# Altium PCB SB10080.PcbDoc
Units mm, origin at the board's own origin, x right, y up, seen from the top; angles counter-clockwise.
Board outline 100 x 80 mm, 2 copper layers (Top Layer, Bottom Layer); 0 components, 0 nets, 4 pads, 0 vias.
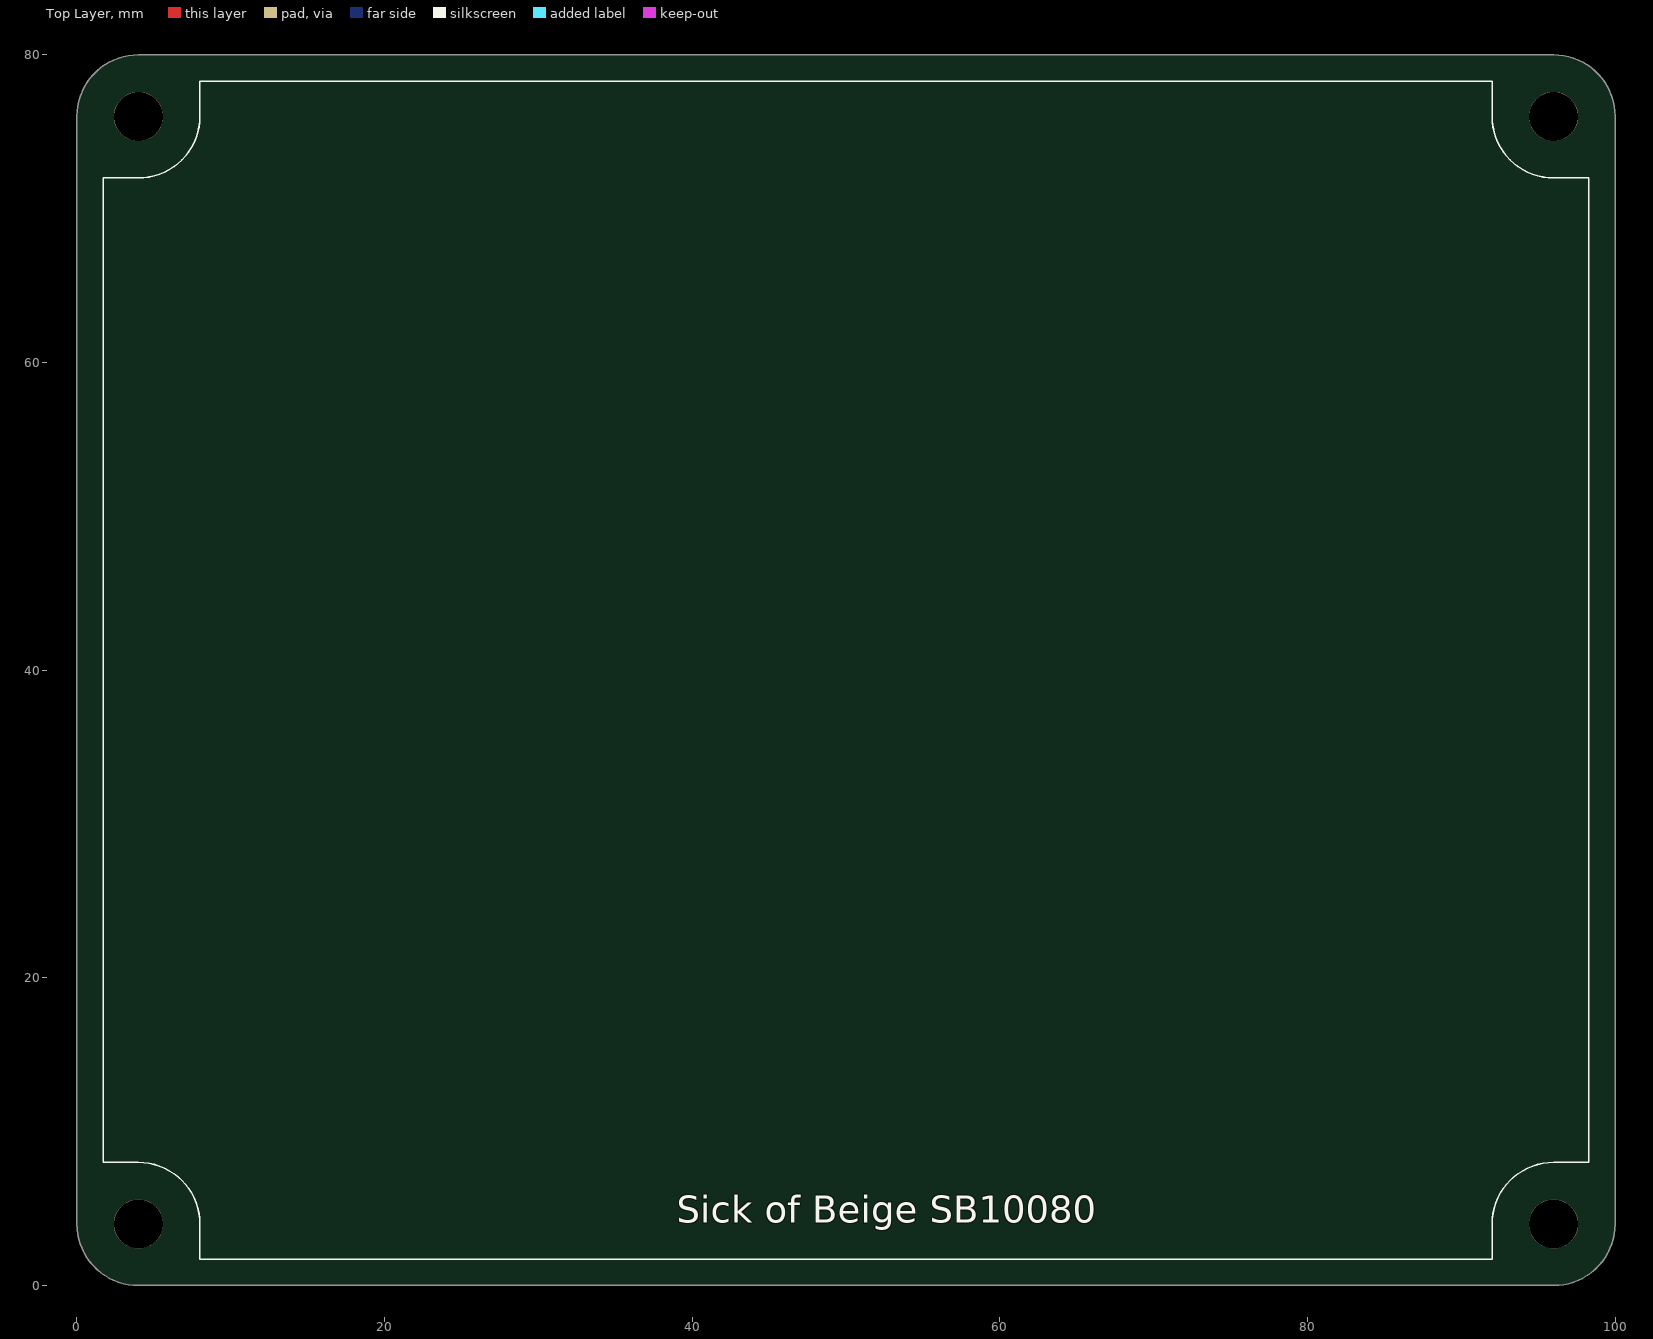
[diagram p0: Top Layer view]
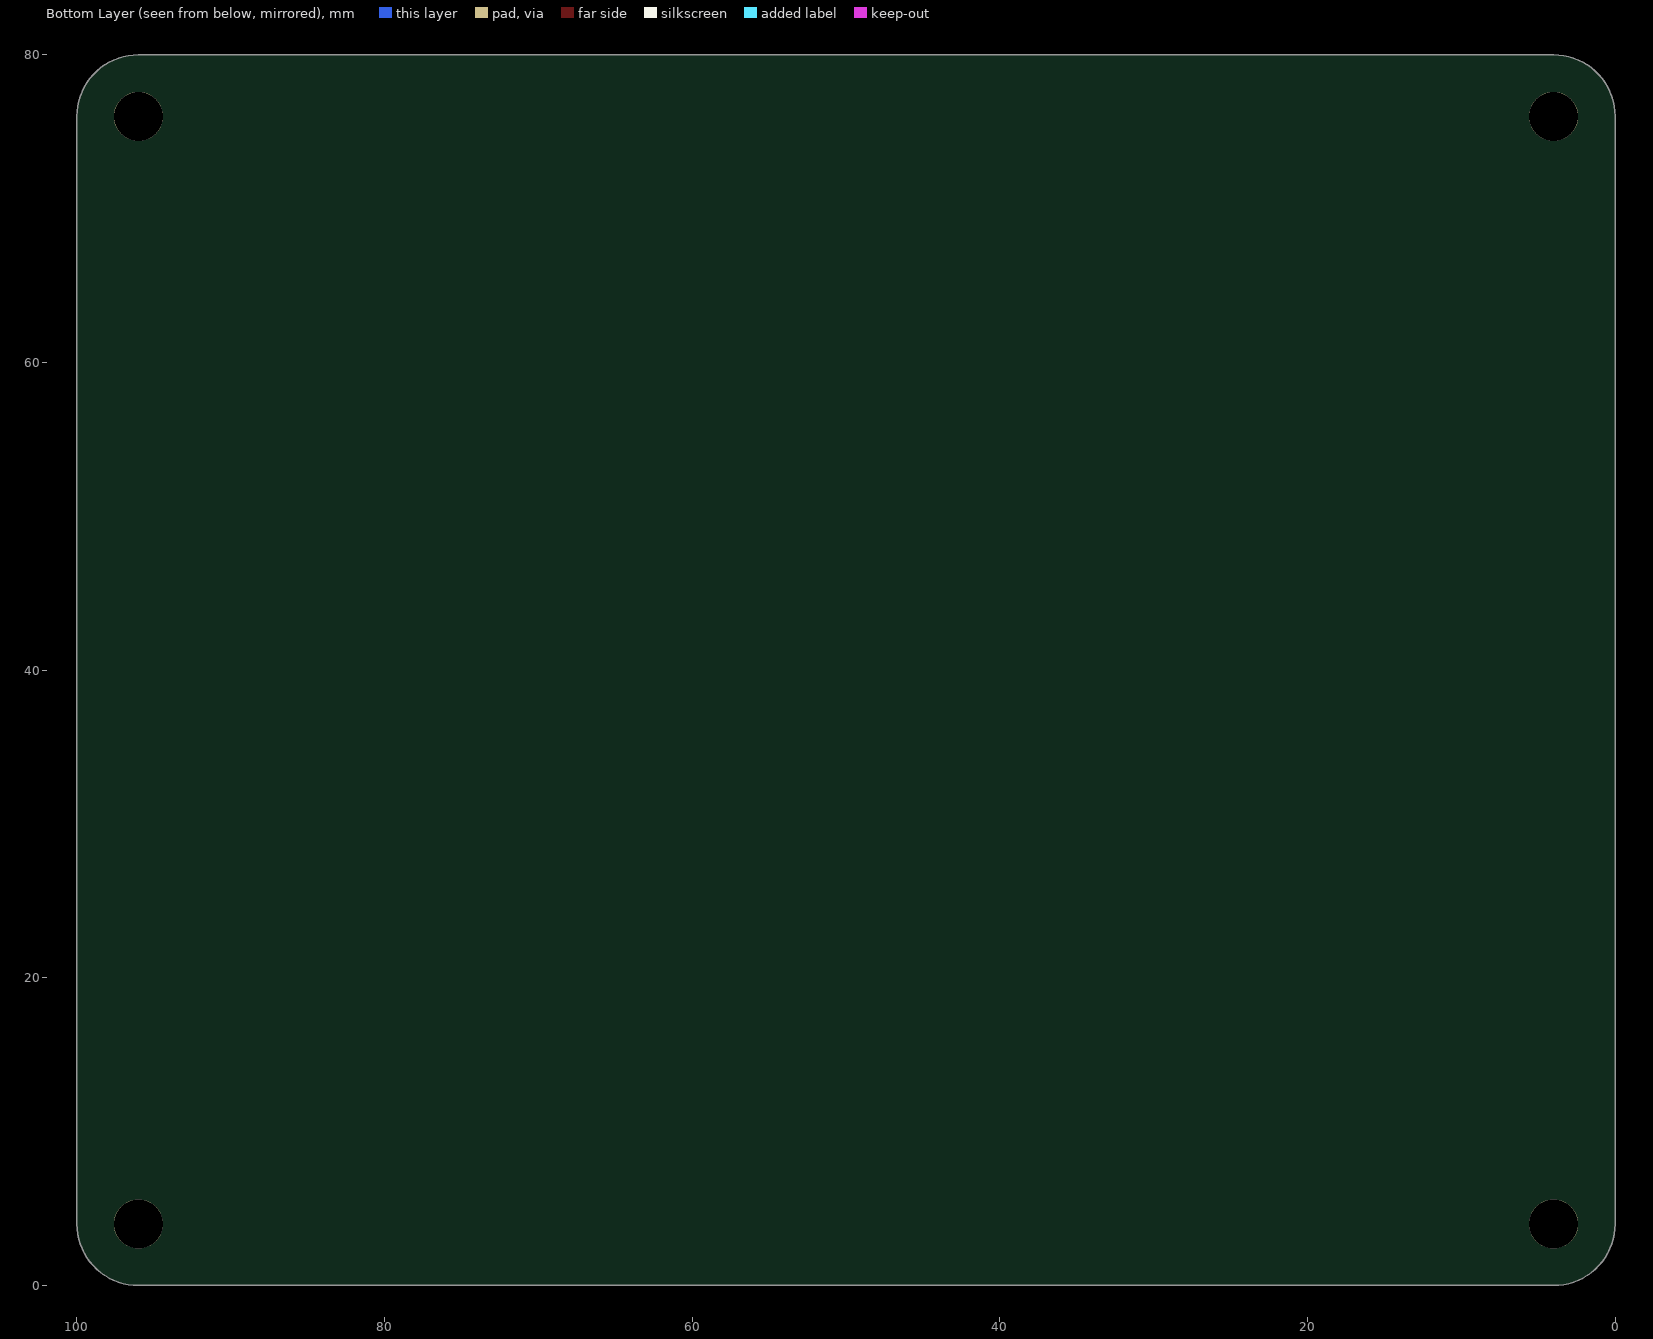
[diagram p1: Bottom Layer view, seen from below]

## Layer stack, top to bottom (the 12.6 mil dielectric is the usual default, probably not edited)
Top Layer: signal copper 0.0356
Dielectric: dielectric 0.32, FR-4, Dk 4.8
Bottom Layer: signal copper 0.0356

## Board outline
0,4 0,76 cw(c4,76) 4,80 96,80 cw(c96,76) 100,76 100,4 cw(c96,4) 96,0 4,0 cw(c4,4)

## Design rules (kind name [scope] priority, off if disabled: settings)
Clearance [All] p1: gap=0.254
PolygonConnect [All] p1: connectstyle=Relief reliefconductorwidth=0.254 reliefentries=4 polygonreliefangle="90 Angle" airgapwidth=0.254
RoutingVias [All] p1: holewidth=0.711 width=1.27 viastyle="Through Hole" minholewidth=0.711 minwidth=1.27 maxholewidth=0.711 maxwidth=1.27
SolderMaskExpansion [All] p1: expansion=0.102
Width [All] p1: maxlimit=0.254 minlimit=0.254 preferedwidth=0.254
28 further rules are at their usual default settings.

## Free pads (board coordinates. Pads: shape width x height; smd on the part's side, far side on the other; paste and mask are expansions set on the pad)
  round 3.2 hole 3.2 unplated: 0(4,4) 1(4,76) 2(96,76) 3(96,4)

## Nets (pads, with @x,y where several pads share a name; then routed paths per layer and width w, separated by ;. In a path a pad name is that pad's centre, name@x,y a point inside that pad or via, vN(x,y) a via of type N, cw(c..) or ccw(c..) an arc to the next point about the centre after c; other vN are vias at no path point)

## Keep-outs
Top Overlay:
  lines w0.102: 1.7,8 4,8 cw(c4,4) 8,4 8,1.7 92,1.7 92,4 cw(c96,4) 96,8 98.3,8 98.3,8.5 98.3,72 96,72 cw(c96,76) 92,76 92,78.3 8,78.3 8,76 cw(c4,76) 4,72 1.7,72 1.7,8

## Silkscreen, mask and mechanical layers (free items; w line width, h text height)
Top Overlay:
  text "Sick of Beige SB10080" at 39,3.5 h3
Mechanical 1:
  the board outline again, w0.102
Mechanical 4:
  circle w0.102: c96,4 r1.6
  circle w0.102: c4,4 r1.6
  circle w0.102: c4,76 r1.6
  circle w0.102: c96,76 r1.6
  lines w0.102: 0,40 100,40 ; 50,0 50,80

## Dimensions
96,80 to 96,0 on Mechanical 3
0,4 to 100,4 on Mechanical 3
